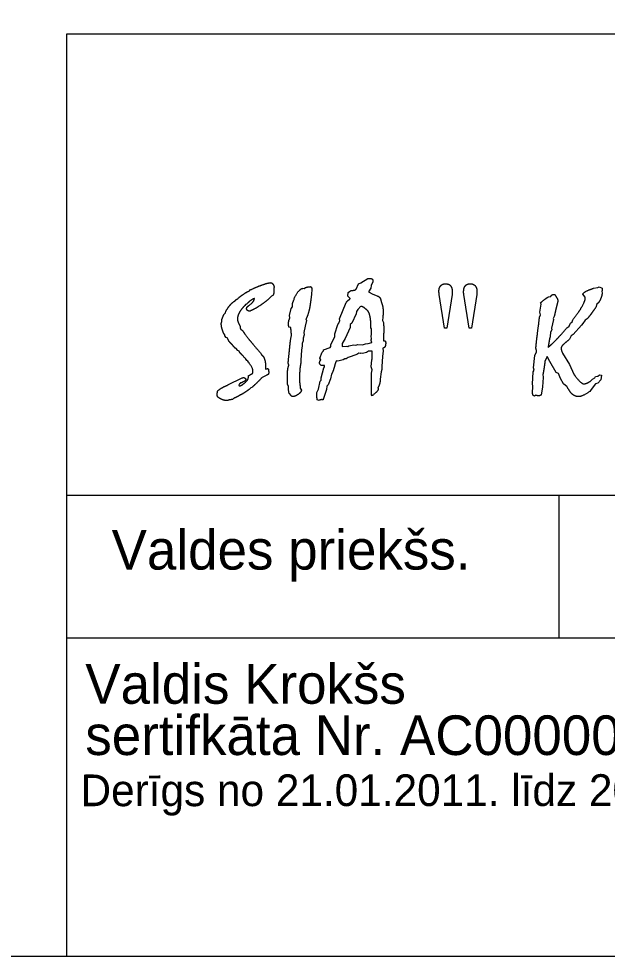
# Model space of a CAD drawing. Extents: x 728492 to 729038, y 272968 to 273171.
# Drawn here: x 728972.1 to 728986.97, y 272986.9 to 273010.57 of the extents above; entities that cross this region are included whole.
import ezdxf

# ---------------------------------------------------------------- set-up
doc = ezdxf.new("R2010")
doc.units = 0
doc.layers.add('RAMI_PLAN_####_TKST_#', color=7, linetype='Continuous')

msp = doc.modelspace()

# ---------------------------------------------------------------- linework, layer by layer
at = {"layer": 'RAMI_PLAN_####_TKST_#'}
for p, q in [((728973.314, 273010.185), (729038.384, 273010.185)), ((728973.314, 272986.902), (728973.314, 273010.185)), ((728973.314, 272998.543), (729011.37, 272998.543)), ((728985.757, 272994.943), (728985.757, 272998.543)), ((728973.314, 272994.943), (729011.37, 272994.943))]:
    msp.add_line(p, q, dxfattribs=at)
msp.add_lwpolyline([(728765.305, 273170.927), (728765.305, 272986.902), (729038.383, 272986.902), (729038.383, 273170.927)], close=True, dxfattribs=at)
for points in [[(728980.624, 273003.747), (728980.689, 273003.876), (728980.744, 273003.9), (728980.923, 273004.014)], [(728981.045, 273003.93), (728981.007, 273003.839), (728980.996, 273003.77), (728980.942, 273003.678), (728981.048, 273003.616), (728981.159, 273003.571)], [(728977.894, 273003.688), (728977.934, 273003.7), (728977.952, 273003.726)], [(728978.552, 273003.791), (728978.552, 273003.784), (728978.548, 273003.787), (728978.548, 273003.729), (728978.545, 273003.707), (728978.543, 273003.701)], [(728979.283, 273003.765), (728979.313, 273003.758), (728979.343, 273003.784)], [(728980.478, 273003.508), (728980.417, 273003.566), (728980.422, 273003.659)], [(728980.491, 273003.706), (728980.495, 273003.708)], [(728986.62, 273003.767), (728986.73, 273003.785), (728986.769, 273003.804), (728986.838, 273003.77), (728986.846, 273003.709), (728986.831, 273003.686), (728986.842, 273003.647)], [(728977.649, 273003.509), (728977.657, 273003.528)], [(728978.522, 273003.586), (728978.489, 273003.565), (728978.472, 273003.546)], [(728979.736, 273001.958), (728979.71, 273002.001), (728979.766, 273002.151), (728979.802, 273002.188), (728979.802, 273002.215), (728979.97, 273002.273), (728979.989, 273002.295), (728979.989, 273002.338), (728980.05, 273002.484), (728980.084, 273002.536), (728980.088, 273002.613), (728980.164, 273002.85), (728980.185, 273002.886), (728980.211, 273002.951), (728980.207, 273002.992), (728980.376, 273003.405)], [(728982.921, 273002.755), (728982.856, 273002.755), (728982.725, 273003.612)], [(728983.05, 273003.61), (728982.921, 273002.755)], [(728983.542, 273002.755), (728983.478, 273002.755), (728983.345, 273003.612)], [(728983.674, 273003.612), (728983.542, 273002.755)], [(728985.258, 273003.036), (728985.284, 273003.096), (728985.269, 273003.161), (728985.299, 273003.361), (728985.288, 273003.395)], [(728985.484, 273003.548), (728985.544, 273003.555)], [(728985.621, 273003.61), (728985.647, 273003.61)], [(728986.413, 273003.537), (728986.353, 273003.613)], [(728986.754, 273003.406), (728986.711, 273003.368), (728986.678, 273003.277)], [(728977.283, 273003.104), (728977.324, 273003.148), (728977.335, 273003.191)], [(728977.857, 273003.363), (728977.829, 273003.356), (728977.814, 273003.328)], [(728977.864, 273003.221), (728977.857, 273003.244)], [(728978.93, 273002.967), (728978.949, 273003.018), (728978.942, 273003.076), (728978.984, 273003.255), (728979.014, 273003.298), (728979.02, 273003.384)], [(728980.744, 273003.31), (728980.667, 273003.233), (728980.632, 273003.175), (728980.628, 273003.119), (728980.521, 273002.882), (728980.475, 273002.85), (728980.475, 273002.774), (728980.349, 273002.499), (728980.277, 273002.372), (728980.273, 273002.295)], [(728980.964, 273003.108), (728980.931, 273003.185)], [(728977.233, 273002.921), (728977.229, 273002.965)], [(728979.359, 273002.992), (728979.371, 273002.951), (728979.339, 273002.809), (728979.305, 273002.648), (728979.309, 273002.594), (728979.287, 273002.506), (728979.29, 273002.441), (728979.266, 273002.368), (728979.266, 273002.315), (728979.247, 273002.203), (728979.225, 273001.947), (728979.229, 273001.882)], [(728981.302, 273003.035), (728981.293, 273002.955), (728981.317, 273002.904)], [(728985.632, 273003.053), (728985.606, 273003), (728985.613, 273002.974), (728985.565, 273002.759), (728985.568, 273002.714), (728985.533, 273002.656), (728985.529, 273002.552)], [(728985.962, 273002.778), (728986.011, 273002.806), (728986.043, 273002.886), (728986.088, 273002.92), (728986.099, 273002.97)], [(728986.467, 273002.996), (728986.409, 273002.963), (728986.357, 273002.875), (728986.317, 273002.832), (728986.112, 273002.602), (728986.061, 273002.565), (728986.018, 273002.477)], [(728977.675, 273002.842), (728977.692, 273002.801), (728977.692, 273002.79), (728977.692, 273002.773)], [(728978.977, 273002.773), (728978.927, 273002.782)], [(728981.015, 273002.495), (728981.007, 273002.549), (728981.015, 273002.609), (728981.015, 273002.74), (728980.996, 273002.766)], [(728977.416, 273002.422), (728977.371, 273002.51), (728977.343, 273002.521), (728977.309, 273002.564), (728977.309, 273002.579)], [(728978.966, 273002.435), (728978.981, 273002.545), (728978.996, 273002.564)], [(728981.317, 273002.488), (728981.317, 273002.437), (728981.362, 273002.437)], [(728977.681, 273002.151), (728977.668, 273002.177), (728977.638, 273002.192), (728977.588, 273002.25), (728977.565, 273002.257)], [(728980.273, 273002.295), (728980.387, 273002.303), (728980.417, 273002.292), (728980.445, 273002.316), (728980.57, 273002.338), (728980.617, 273002.327), (728980.667, 273002.346), (728980.785, 273002.335), (728980.865, 273002.364), (728980.931, 273002.372), (728981.026, 273002.396)], [(728981.297, 273002.247), (728981.31, 273002.185), (728981.293, 273002.043), (728981.271, 273001.794), (728981.274, 273001.718), (728981.256, 273001.656), (728981.23, 273001.469), (728981.23, 273001.432)], [(728985.167, 273001.063), (728985.135, 273001.04), (728985.098, 273001.059), (728985.079, 273001.113), (728985.09, 273001.304), (728985.079, 273001.341), (728985.101, 273001.656), (728985.12, 273001.699), (728985.109, 273001.753), (728985.139, 273002.067), (728985.185, 273002.163), (728985.182, 273002.193), (728985.167, 273002.251)], [(728981.03, 273001.053), (728981.015, 273001.075), (728981.015, 273001.266), (728981.011, 273001.495), (728981.015, 273001.619), (728981.03, 273001.707), (728981.007, 273001.783), (728981.022, 273001.962), (728981.033, 273001.987), (728981.03, 273002.181), (728980.942, 273002.177), (728980.884, 273002.142), (728980.785, 273002.115), (728980.744, 273002.13), (728980.727, 273002.115), (728980.693, 273002.127), (728980.643, 273002.097), (728980.422, 273002.02), (728980.376, 273001.986), (728980.336, 273001.986), (728980.299, 273001.958), (728980.161, 273001.924), (728980.131, 273001.932)], [(728985.955, 273001.278), (728985.867, 273001.351), (728985.787, 273001.487), (728985.736, 273001.611), (728985.682, 273001.637), (728985.518, 273001.914), (728985.452, 273002.043), (728985.396, 273001.914)], [(728985.817, 273002.193), (728985.843, 273002.127), (728986.015, 273001.837), (728986.127, 273001.596)], [(728978.927, 273001.82), (728978.908, 273001.874)], [(728979.634, 273001.137), (728979.671, 273001.221), (728979.718, 273001.418), (728979.744, 273001.446), (728979.74, 273001.502), (728979.809, 273001.756), (728979.828, 273001.786), (728979.824, 273001.816), (728979.748, 273001.812)], [(728977.36, 273001.312), (728977.382, 273001.331), (728977.75, 273001.501)], [(728977.902, 273001.503), (728977.902, 273001.516), (728977.902, 273001.531)], [(728978.354, 273001.564), (728978.248, 273001.512), (728978.231, 273001.495)], [(728978.332, 273001.723), (728978.369, 273001.732)], [(728978.412, 273001.714), (728978.412, 273001.684)], [(728978.936, 273001.112), (728978.916, 273001.202), (728978.919, 273001.286), (728978.893, 273001.346), (728978.893, 273001.454), (728978.893, 273001.596), (728978.893, 273001.63)], [(728980.004, 273001.596), (728979.974, 273001.48), (728979.92, 273001.327), (728979.886, 273001.29), (728979.875, 273001.209)], [(728985.346, 273001.596), (728985.35, 273001.512), (728985.331, 273001.274), (728985.303, 273001.07)], [(728986.558, 273001.428), (728986.601, 273001.473), (728986.654, 273001.503), (728986.674, 273001.542), (728986.734, 273001.55), (728986.773, 273001.583), (728986.823, 273001.568), (728986.81, 273001.458), (728986.73, 273001.37), (728986.67, 273001.355), (728986.562, 273001.212), (728986.528, 273001.158), (728986.517, 273001.15)], [(728977.672, 273001.338), (728977.659, 273001.318)], [(728977.791, 273001.411), (728977.769, 273001.404), (728977.741, 273001.381)], [(728977.993, 273001.262), (728977.964, 273001.25), (728977.934, 273001.22)], [(728979.214, 273001.28), (728979.214, 273001.243), (728979.244, 273001.197)], [(728977.137, 273001.013), (728977.116, 273001.052)], [(728977.124, 273001.142), (728977.122, 273001.159)], [(728977.715, 273001.074), (728977.707, 273001.078)], [(728977.367, 273000.928), (728977.35, 273000.932), (728977.339, 273000.932)], [(728977.558, 273000.998), (728977.539, 273000.979), (728977.515, 273000.971), (728977.498, 273000.956)], [(728979.688, 273000.935), (728979.645, 273000.95)]]:
    msp.add_lwpolyline(points, dxfattribs=at)
for points in [[(728978.246, 273003.849), (728978.363, 273003.892), (728978.438, 273003.903)], [(728978.438, 273003.903), (728978.446, 273003.905), (728978.452, 273003.906)], [(728978.452, 273003.906), (728978.459, 273003.907), (728978.464, 273003.907)], [(728978.464, 273003.907), (728978.502, 273003.907), (728978.527, 273003.866)], [(728978.527, 273003.866), (728978.552, 273003.825), (728978.552, 273003.791)], [(728980.923, 273004.014), (728981.009, 273004.014), (728981.029, 273004.001)], [(728981.029, 273004.001), (728981.048, 273003.988), (728981.048, 273003.945)], [(728981.047, 273003.936), (728981.046, 273003.932), (728981.045, 273003.93)], [(728981.048, 273003.945), (728981.048, 273003.94), (728981.047, 273003.936)], [(728982.762, 273003.829), (728982.807, 273003.879), (728982.886, 273003.879)], [(728982.886, 273003.879), (728982.968, 273003.879), (728983.011, 273003.828)], [(728983.384, 273003.828), (728983.427, 273003.879), (728983.508, 273003.879)], [(728983.508, 273003.879), (728983.587, 273003.879), (728983.632, 273003.829)], [(728977.657, 273003.528), (728977.735, 273003.586), (728977.862, 273003.668)], [(728977.862, 273003.668), (728977.885, 273003.681), (728977.894, 273003.688)], [(728977.952, 273003.726), (728978.128, 273003.806), (728978.246, 273003.849)], [(728978.545, 273003.653), (728978.545, 273003.642), (728978.539, 273003.625)], [(728978.543, 273003.701), (728978.543, 273003.688), (728978.544, 273003.677)], [(728978.544, 273003.677), (728978.545, 273003.666), (728978.545, 273003.653)], [(728979.048, 273003.463), (728979.143, 273003.732), (728979.283, 273003.765)], [(728979.343, 273003.784), (728979.384, 273003.795), (728979.415, 273003.801)], [(728979.415, 273003.801), (728979.447, 273003.806), (728979.47, 273003.806)], [(728979.507, 273003.715), (728979.477, 273003.393), (728979.444, 273003.24)], [(728979.47, 273003.806), (728979.488, 273003.806), (728979.498, 273003.784)], [(728979.498, 273003.784), (728979.507, 273003.761), (728979.507, 273003.715)], [(728980.422, 273003.659), (728980.45, 273003.672), (728980.491, 273003.706)], [(728980.495, 273003.708), (728980.51, 273003.71), (728980.538, 273003.712)], [(728980.538, 273003.712), (728980.604, 273003.715), (728980.624, 273003.747)], [(728982.718, 273003.689), (728982.718, 273003.779), (728982.762, 273003.829)], [(728982.719, 273003.661), (728982.718, 273003.678), (728982.718, 273003.689)], [(728982.725, 273003.612), (728982.721, 273003.644), (728982.719, 273003.661)], [(728983.011, 273003.828), (728983.054, 273003.777), (728983.054, 273003.681)], [(728983.053, 273003.637), (728983.052, 273003.623), (728983.05, 273003.61)], [(728983.054, 273003.681), (728983.054, 273003.651), (728983.053, 273003.637)], [(728983.342, 273003.681), (728983.342, 273003.777), (728983.384, 273003.828)], [(728983.343, 273003.639), (728983.342, 273003.653), (728983.342, 273003.681)], [(728983.345, 273003.612), (728983.344, 273003.625), (728983.343, 273003.639)], [(728983.632, 273003.829), (728983.678, 273003.779), (728983.678, 273003.689)], [(728983.677, 273003.643), (728983.676, 273003.627), (728983.674, 273003.612)], [(728983.678, 273003.689), (728983.678, 273003.659), (728983.677, 273003.643)], [(728986.353, 273003.613), (728986.375, 273003.673), (728986.519, 273003.727)], [(728986.519, 273003.727), (728986.583, 273003.75), (728986.62, 273003.767)], [(728986.842, 273003.647), (728986.837, 273003.589), (728986.815, 273003.53)], [(728977.453, 273003.355), (728977.507, 273003.416), (728977.565, 273003.447)], [(728977.565, 273003.447), (728977.578, 273003.466), (728977.597, 273003.48)], [(728977.597, 273003.48), (728977.616, 273003.494), (728977.649, 273003.509)], [(728977.97, 273003.462), (728977.922, 273003.429), (728977.857, 273003.363)], [(728977.917, 273003.33), (728978.055, 273003.43), (728978.055, 273003.505)], [(728978.055, 273003.505), (728978.018, 273003.496), (728977.97, 273003.462)], [(728978.472, 273003.546), (728978.347, 273003.43), (728978.209, 273003.337)], [(728978.539, 273003.625), (728978.534, 273003.608), (728978.522, 273003.586)], [(728979.02, 273003.384), (728979.029, 273003.41), (728979.048, 273003.463)], [(728980.376, 273003.405), (728980.392, 273003.441), (728980.433, 273003.467)], [(728980.433, 273003.467), (728980.473, 273003.493), (728980.478, 273003.508)], [(728981.159, 273003.571), (728981.202, 273003.562), (728981.225, 273003.528)], [(728981.225, 273003.528), (728981.248, 273003.493), (728981.259, 273003.422)], [(728981.259, 273003.422), (728981.286, 273003.358), (728981.298, 273003.294)], [(728985.288, 273003.395), (728985.325, 273003.436), (728985.375, 273003.475)], [(728985.375, 273003.475), (728985.424, 273003.514), (728985.484, 273003.548)], [(728985.544, 273003.555), (728985.559, 273003.587), (728985.574, 273003.598)], [(728985.574, 273003.598), (728985.589, 273003.61), (728985.621, 273003.61)], [(728985.647, 273003.61), (728985.658, 273003.583), (728985.69, 273003.534)], [(728985.69, 273003.534), (728985.721, 273003.484), (728985.721, 273003.449)], [(728985.71, 273003.391), (728985.707, 273003.378), (728985.707, 273003.372)], [(728985.721, 273003.449), (728985.721, 273003.432), (728985.71, 273003.391)], [(728986.328, 273003.295), (728986.416, 273003.453), (728986.416, 273003.522)], [(728986.416, 273003.532), (728986.416, 273003.535), (728986.413, 273003.537)], [(728986.416, 273003.522), (728986.416, 273003.529), (728986.416, 273003.532)], [(728986.815, 273003.53), (728986.794, 273003.471), (728986.754, 273003.406)], [(728977.335, 273003.191), (728977.399, 273003.294), (728977.453, 273003.355)], [(728977.814, 273003.328), (728977.72, 273003.236), (728977.674, 273003.152)], [(728977.857, 273003.244), (728977.857, 273003.259), (728977.862, 273003.273)], [(728977.862, 273003.273), (728977.868, 273003.287), (728977.879, 273003.302)], [(728977.896, 273003.196), (728977.879, 273003.204), (728977.864, 273003.221)], [(728977.879, 273003.302), (728977.894, 273003.313), (728977.917, 273003.33)], [(728977.926, 273003.188), (728977.913, 273003.188), (728977.896, 273003.196)], [(728977.938, 273003.189), (728977.934, 273003.188), (728977.926, 273003.188)], [(728977.948, 273003.191), (728977.943, 273003.189), (728977.938, 273003.189)], [(728978.209, 273003.337), (728978.072, 273003.244), (728977.948, 273003.191)], [(728979.444, 273003.24), (728979.412, 273003.087), (728979.359, 273002.992)], [(728980.822, 273003.278), (728980.785, 273003.302), (728980.744, 273003.31)], [(728980.931, 273003.185), (728980.86, 273003.254), (728980.822, 273003.278)], [(728981.298, 273003.294), (728981.31, 273003.23), (728981.31, 273003.149)], [(728985.668, 273003.224), (728985.651, 273003.146), (728985.632, 273003.053)], [(728985.707, 273003.372), (728985.686, 273003.301), (728985.668, 273003.224)], [(728986.099, 273002.97), (728986.239, 273003.137), (728986.328, 273003.295)], [(728986.678, 273003.277), (728986.607, 273003.178), (728986.56, 273003.115)], [(728977.221, 273002.894), (728977.225, 273002.907), (728977.233, 273002.921)], [(728977.229, 273002.965), (728977.234, 273002.98), (728977.254, 273003.028)], [(728977.254, 273003.028), (728977.274, 273003.076), (728977.283, 273003.104)], [(728977.674, 273003.152), (728977.627, 273003.068), (728977.627, 273002.988)], [(728977.627, 273002.988), (728977.627, 273002.956), (728977.639, 273002.921)], [(728977.639, 273002.921), (728977.651, 273002.885), (728977.675, 273002.842)], [(728978.916, 273002.878), (728978.916, 273002.889), (728978.925, 273002.936)], [(728978.925, 273002.936), (728978.929, 273002.956), (728978.93, 273002.967)], [(728980.99, 273002.974), (728980.981, 273003.046), (728980.964, 273003.108)], [(728981, 273002.846), (728981, 273002.901), (728980.99, 273002.974)], [(728981.304, 273003.08), (728981.302, 273003.05), (728981.302, 273003.035)], [(728981.31, 273003.149), (728981.31, 273003.134), (728981.304, 273003.08)], [(728985.212, 273002.656), (728985.247, 273002.918), (728985.258, 273003.036)], [(728986.56, 273003.115), (728986.513, 273003.053), (728986.467, 273002.996)], [(728977.218, 273002.87), (728977.218, 273002.881), (728977.221, 273002.894)], [(728977.236, 273002.75), (728977.218, 273002.818), (728977.218, 273002.87)], [(728977.291, 273002.601), (728977.255, 273002.681), (728977.236, 273002.75)], [(728977.692, 273002.773), (728977.692, 273002.754), (728977.708, 273002.736)], [(728977.708, 273002.736), (728977.724, 273002.717), (728977.748, 273002.709)], [(728977.748, 273002.709), (728977.799, 273002.625), (728977.919, 273002.475)], [(728978.918, 273002.838), (728978.916, 273002.861), (728978.916, 273002.878)], [(728978.927, 273002.782), (728978.921, 273002.814), (728978.918, 273002.838)], [(728978.984, 273002.676), (728978.979, 273002.726), (728978.977, 273002.773)], [(728980.996, 273002.766), (728980.998, 273002.789), (728980.999, 273002.806)], [(728980.999, 273002.806), (728981, 273002.824), (728981, 273002.846)], [(728981.317, 273002.904), (728981.317, 273002.888), (728981.319, 273002.858)], [(728981.319, 273002.858), (728981.325, 273002.757), (728981.325, 273002.725)], [(728981.325, 273002.725), (728981.325, 273002.695), (728981.321, 273002.616)], [(728985.709, 273002.495), (728985.83, 273002.621), (728985.962, 273002.778)], [(728977.305, 273002.594), (728977.3, 273002.599), (728977.291, 273002.601)], [(728977.309, 273002.579), (728977.309, 273002.588), (728977.305, 273002.594)], [(728977.919, 273002.475), (728978.038, 273002.325), (728978.22, 273002.119)], [(728978.996, 273002.564), (728978.988, 273002.626), (728978.984, 273002.676)], [(728981.007, 273002.448), (728981.007, 273002.46), (728981.013, 273002.484)], [(728981.011, 273002.433), (728981.007, 273002.445), (728981.007, 273002.448)], [(728981.013, 273002.484), (728981.013, 273002.49), (728981.015, 273002.495)], [(728981.321, 273002.616), (728981.317, 273002.536), (728981.317, 273002.488)], [(728985.167, 273002.251), (728985.178, 273002.395), (728985.212, 273002.656)], [(728985.477, 273002.273), (728985.589, 273002.368), (728985.709, 273002.495)], [(728985.504, 273002.444), (728985.492, 273002.381), (728985.477, 273002.273)], [(728985.529, 273002.552), (728985.516, 273002.507), (728985.504, 273002.444)], [(728986.018, 273002.477), (728985.903, 273002.387), (728985.852, 273002.334)], [(728977.492, 273002.341), (728977.455, 273002.383), (728977.416, 273002.422)], [(728977.565, 273002.257), (728977.53, 273002.3), (728977.492, 273002.341)], [(728978.908, 273001.874), (728978.932, 273002.106), (728978.944, 273002.221)], [(728978.944, 273002.221), (728978.955, 273002.336), (728978.966, 273002.435)], [(728981.026, 273002.396), (728981.015, 273002.42), (728981.011, 273002.433)], [(728981.334, 273002.268), (728981.321, 273002.258), (728981.297, 273002.247)], [(728981.358, 273002.292), (728981.347, 273002.278), (728981.334, 273002.268)], [(728981.364, 273002.316), (728981.36, 273002.301), (728981.358, 273002.292)], [(728981.362, 273002.437), (728981.37, 273002.411), (728981.372, 273002.397)], [(728981.373, 273002.372), (728981.373, 273002.357), (728981.364, 273002.316)], [(728981.372, 273002.397), (728981.373, 273002.383), (728981.373, 273002.372)], [(728985.852, 273002.334), (728985.802, 273002.281), (728985.802, 273002.247)], [(728985.802, 273002.247), (728985.802, 273002.234), (728985.811, 273002.209)], [(728985.811, 273002.209), (728985.815, 273002.198), (728985.817, 273002.193)], [(728977.756, 273002.069), (728977.707, 273002.121), (728977.681, 273002.151)], [(728978.018, 273001.68), (728978.018, 273001.792), (728977.756, 273002.069)], [(728978.22, 273002.119), (728978.227, 273002.099), (728978.24, 273002.083)], [(728978.24, 273002.083), (728978.253, 273002.067), (728978.278, 273002.05)], [(728978.278, 273002.05), (728978.307, 273001.996), (728978.321, 273001.943)], [(728978.321, 273001.943), (728978.335, 273001.889), (728978.335, 273001.824)], [(728978.335, 273001.769), (728978.334, 273001.746), (728978.332, 273001.723)], [(728978.335, 273001.824), (728978.335, 273001.792), (728978.335, 273001.769)], [(728978.369, 273001.732), (728978.373, 273001.734), (728978.378, 273001.737)], [(728978.378, 273001.737), (728978.382, 273001.74), (728978.384, 273001.74)], [(728978.384, 273001.74), (728978.393, 273001.74), (728978.401, 273001.732)], [(728978.893, 273001.63), (728978.893, 273001.693), (728978.902, 273001.738)], [(728978.902, 273001.738), (728978.91, 273001.783), (728978.927, 273001.82)], [(728979.229, 273001.882), (728979.21, 273001.8), (728979.202, 273001.699)], [(728979.701, 273001.885), (728979.703, 273001.904), (728979.709, 273001.919)], [(728979.712, 273001.849), (728979.701, 273001.867), (728979.701, 273001.885)], [(728979.709, 273001.919), (728979.716, 273001.934), (728979.736, 273001.958)], [(728979.748, 273001.812), (728979.723, 273001.831), (728979.712, 273001.849)], [(728980.081, 273001.805), (728980.052, 273001.689), (728980.004, 273001.596)], [(728980.131, 273001.932), (728980.11, 273001.921), (728980.081, 273001.805)], [(728985.396, 273001.914), (728985.382, 273001.802), (728985.369, 273001.727)], [(728977.75, 273001.501), (728977.76, 273001.506), (728977.768, 273001.509)], [(728977.768, 273001.509), (728977.776, 273001.512), (728977.784, 273001.512)], [(728977.784, 273001.512), (728977.801, 273001.512), (728977.819, 273001.494)], [(728977.813, 273001.378), (728977.902, 273001.454), (728977.902, 273001.503)], [(728977.902, 273001.531), (728977.902, 273001.538), (728977.905, 273001.547)], [(728977.905, 273001.547), (728977.907, 273001.555), (728977.913, 273001.564)], [(728977.913, 273001.564), (728977.941, 273001.577), (728977.967, 273001.592)], [(728977.967, 273001.592), (728977.993, 273001.607), (728978.014, 273001.622)], [(728978.014, 273001.622), (728978.016, 273001.635), (728978.017, 273001.647)], [(728978.017, 273001.647), (728978.018, 273001.66), (728978.018, 273001.68)], [(728978.402, 273001.593), (728978.388, 273001.577), (728978.354, 273001.564)], [(728978.401, 273001.732), (728978.408, 273001.725), (728978.412, 273001.714)], [(728978.42, 273001.637), (728978.416, 273001.609), (728978.402, 273001.593)], [(728978.412, 273001.684), (728978.412, 273001.68), (728978.415, 273001.665)], [(728978.415, 273001.665), (728978.418, 273001.65), (728978.42, 273001.637)], [(728979.202, 273001.699), (728979.195, 273001.598), (728979.195, 273001.443)], [(728985.369, 273001.727), (728985.357, 273001.652), (728985.346, 273001.596)], [(728986.127, 273001.596), (728986.138, 273001.58), (728986.16, 273001.55)], [(728986.16, 273001.55), (728986.31, 273001.352), (728986.379, 273001.352)], [(728977.192, 273001.226), (728977.26, 273001.271), (728977.36, 273001.312)], [(728977.659, 273001.318), (728977.66, 273001.314), (728977.666, 273001.308)], [(728977.666, 273001.308), (728977.677, 273001.301), (728977.685, 273001.301)], [(728977.696, 273001.368), (728977.681, 273001.359), (728977.672, 273001.338)], [(728977.685, 273001.301), (728977.724, 273001.301), (728977.813, 273001.378)], [(728977.741, 273001.381), (728977.711, 273001.378), (728977.696, 273001.368)], [(728977.826, 273001.436), (728977.814, 273001.422), (728977.791, 273001.411)], [(728977.819, 273001.494), (728977.838, 273001.477), (728977.838, 273001.465)], [(728977.838, 273001.465), (728977.838, 273001.45), (728977.826, 273001.436)], [(728978.129, 273001.389), (728978.072, 273001.333), (728977.993, 273001.262)], [(728978.231, 273001.495), (728978.186, 273001.445), (728978.129, 273001.389)], [(728979.195, 273001.443), (728979.195, 273001.415), (728979.199, 273001.378)], [(728979.199, 273001.378), (728979.202, 273001.34), (728979.214, 273001.28)], [(728981.216, 273001.347), (728981.203, 273001.303), (728981.175, 273001.254)], [(728981.23, 273001.432), (728981.23, 273001.39), (728981.216, 273001.347)], [(728986.076, 273001.1), (728986.026, 273001.147), (728985.955, 273001.278)], [(728986.379, 273001.352), (728986.407, 273001.352), (728986.452, 273001.37)], [(728986.452, 273001.37), (728986.497, 273001.389), (728986.558, 273001.428)], [(728977.113, 273001.086), (728977.113, 273001.103), (728977.115, 273001.117)], [(728977.114, 273001.07), (728977.113, 273001.082), (728977.113, 273001.086)], [(728977.116, 273001.052), (728977.116, 273001.058), (728977.114, 273001.07)], [(728977.115, 273001.117), (728977.118, 273001.131), (728977.124, 273001.142)], [(728977.122, 273001.159), (728977.124, 273001.181), (728977.192, 273001.226)], [(728977.641, 273001.035), (728977.606, 273001.016), (728977.558, 273000.998)], [(728977.707, 273001.078), (728977.675, 273001.054), (728977.641, 273001.035)], [(728977.819, 273001.139), (728977.765, 273001.104), (728977.715, 273001.074)], [(728977.934, 273001.22), (728977.872, 273001.175), (728977.819, 273001.139)], [(728978.976, 273001.062), (728978.955, 273001.095), (728978.936, 273001.112)], [(728979.018, 273001.029), (728978.998, 273001.029), (728978.976, 273001.062)], [(728979.073, 273001.039), (728979.044, 273001.029), (728979.018, 273001.029)], [(728979.141, 273001.074), (728979.102, 273001.049), (728979.073, 273001.039)], [(728979.214, 273001.132), (728979.191, 273001.104), (728979.141, 273001.074)], [(728979.244, 273001.197), (728979.236, 273001.16), (728979.214, 273001.132)], [(728979.63, 273001.086), (728979.63, 273001.107), (728979.631, 273001.118)], [(728979.633, 273001.033), (728979.63, 273001.062), (728979.63, 273001.086)], [(728979.631, 273001.118), (728979.632, 273001.129), (728979.634, 273001.137)], [(728979.645, 273000.95), (728979.636, 273001.004), (728979.633, 273001.033)], [(728979.827, 273001.061), (728979.807, 273001), (728979.791, 273000.95)], [(728979.875, 273001.209), (728979.847, 273001.122), (728979.827, 273001.061)], [(728981.052, 273001.07), (728981.037, 273001.058), (728981.03, 273001.053)], [(728981.183, 273001.221), (728981.183, 273001.168), (728981.052, 273001.07)], [(728981.175, 273001.254), (728981.179, 273001.245), (728981.181, 273001.235)], [(728981.181, 273001.235), (728981.183, 273001.224), (728981.183, 273001.221)], [(728985.189, 273001.057), (728985.174, 273001.061), (728985.167, 273001.063)], [(728985.236, 273001.048), (728985.223, 273001.048), (728985.189, 273001.057)], [(728985.264, 273001.053), (728985.247, 273001.048), (728985.236, 273001.048)], [(728985.303, 273001.07), (728985.281, 273001.059), (728985.264, 273001.053)], [(728986.198, 273001.036), (728986.127, 273001.053), (728986.076, 273001.1)], [(728986.227, 273001.031), (728986.215, 273001.033), (728986.198, 273001.036)], [(728986.248, 273001.029), (728986.239, 273001.029), (728986.227, 273001.031)], [(728986.517, 273001.15), (728986.327, 273001.029), (728986.248, 273001.029)], [(728977.248, 273000.952), (728977.199, 273000.971), (728977.137, 273001.013)], [(728977.339, 273000.932), (728977.298, 273000.932), (728977.248, 273000.952)], [(728977.428, 273000.946), (728977.395, 273000.94), (728977.367, 273000.928)], [(728977.498, 273000.956), (728977.461, 273000.953), (728977.428, 273000.946)], [(728979.722, 273000.947), (728979.705, 273000.943), (728979.688, 273000.935)], [(728979.755, 273000.954), (728979.738, 273000.952), (728979.722, 273000.947)], [(728979.778, 273000.952), (728979.77, 273000.954), (728979.755, 273000.954)], [(728979.791, 273000.95), (728979.785, 273000.95), (728979.778, 273000.952)]]:
    msp.add_open_spline(points, degree=2, dxfattribs=at)

# ---------------------------------------------------------------- texts
for s, height, rotation, p in [('Valdes priekšs.', 1, 359.9999, (728974.448, 272996.664)), ('Valdis Krokšs', 1, 359.9999, (728973.783, 272993.276)), ('sertifkāta Nr. AC000000071', 1, 359.9999, (728973.783, 272991.982)), ('Derīgs no 21.01.2011. līdz 20.01.2016.', 0.8, 0.0269, (728973.662, 272990.69))]:
    msp.add_text(s, height=height, rotation=rotation, dxfattribs=at).set_placement(p)

doc.saveas('drawing.dxf')
